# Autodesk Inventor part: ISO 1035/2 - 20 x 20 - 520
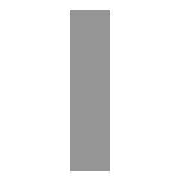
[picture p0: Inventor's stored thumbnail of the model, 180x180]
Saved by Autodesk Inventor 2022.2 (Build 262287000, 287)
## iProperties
_CCFamilyMember: 168
_CCFamilyDisplayName: ISO 1035/2 - 1980 - Barre in acciaio laminate a caldo - Parte 2: barre quadre
_FrameMemberDoc: Frame Member File
_Version: 25.0.0
_GetPNFromCC: 1
Created: 2025-02
Part Number: ISO 1035/2 - 20 x 20 - 520
Material: Acciaio, Dolce
Description: Barre in acciaio laminate a caldo - Parte 2: barre quadre
Document SubType Name: Modeling
Standard: ISO 1035/2
Designer: 18907419
Standard Revision: First edition 1980-10-15
Standards Organization: ISO
Language: it-IT
Size Designation: 20x 20
Categories: <MemberInstance><Categories><Category DisplayName="Forme strutturali" InternalName="089c4875-fa83-4c05-b084-43b9cc11f5ed" Mnemonic="GRDR"><CategoryParameter Dis
Stock Number: 20x 20
Density: 7.85 g/cm^3
Appearance: Semilucidato
IsCustomPart: 1
G_L: 520,000 mm
G_W: 20,000 mm
G_H: 20,000 mm
+D8BF1E54-B56E-453A-8C5C-CEB3DD3A30D1+CUTDETAIL1: Angolo retto 45,00 gr
+D24304F4-30FF-4AC0-819F-7BAAFB98F68D+CUTDETAIL2: Angolo retto 45,00 gr
+DA77D3CE-99E9-4971-B3F3-0C309E4B7C90+CUTDETAIL3: Angolo retto 45,00 gr
+6B59C954-9796-4C30-8DAD-3A38A1700938+CUTDETAIL4: Angolo retto 45,00 gr
Author: 18907419
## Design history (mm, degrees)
node "Piano iniziale"
node "Piano finale"
sketch "Schizzo"
  geometry: L1 (10, -10)-(-10, -10); L2 (-10, -10)-(-10, 10); L3 (-10, 10)-(10, 10); L4 (10, 10)-(10, -10); L5 (-6, 0)-(8, 0); L6 (0, -30)-(0, 40); L7 (0, 54)-(0, -44) reference; L8 (-14, 0)-(14, 0) reference
  constraints: 12 end point, 2 collinear, 2 parallel, 1 horizontal, 1 perpendicular
  dimensions: "d0" = 20 distance between parallel lines of L3 L1 (= G_W); "d1" = 20 distance between parallel lines of L4 L2 (= G_H); "d4" = 10 distance between parallel lines of L6 L4 (= 0.5 x d1); "d5" = 10 distance between parallel lines of L5 L3 (= 0.5 x d0)
extrude "Corpo" new body sketch "Schizzo" stored distance "d2" = 520 (= G_L); taper "d3" = 0 deg
node "Driven Length"
  sketch "Sketch3"
    geometry: L1 (0, 0)-(10, 0) reference
    constraints: 2 end point, 1 horizontal
  workplane "Work Plane3"
  sketch "Sketch4"
    geometry: L1 (-2, -10)-(12, -10) reference; L2 (-2, 510)-(12, 510) reference
    dimensions: "d9" = 520 dimension on L1 L2 (derived)
node "Piano di lavoro4"
feature "Divisione1"
node "Piano di lavoro5"
feature "Divisione2"
node "Piano di lavoro6"
feature "Divisione3"
node "Piano di lavoro7"
feature "Divisione4"
body "Solid1"
other parameters: "G_W" = 20 [user parameter; used in 1 equation term], "G_H" = 20 [user parameter; used in 1 equation term], "G_L" = 520 (= d9) [user parameter; used in 1 equation term], "d8" = 90 deg
